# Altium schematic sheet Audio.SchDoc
size A4; Revision: C.2
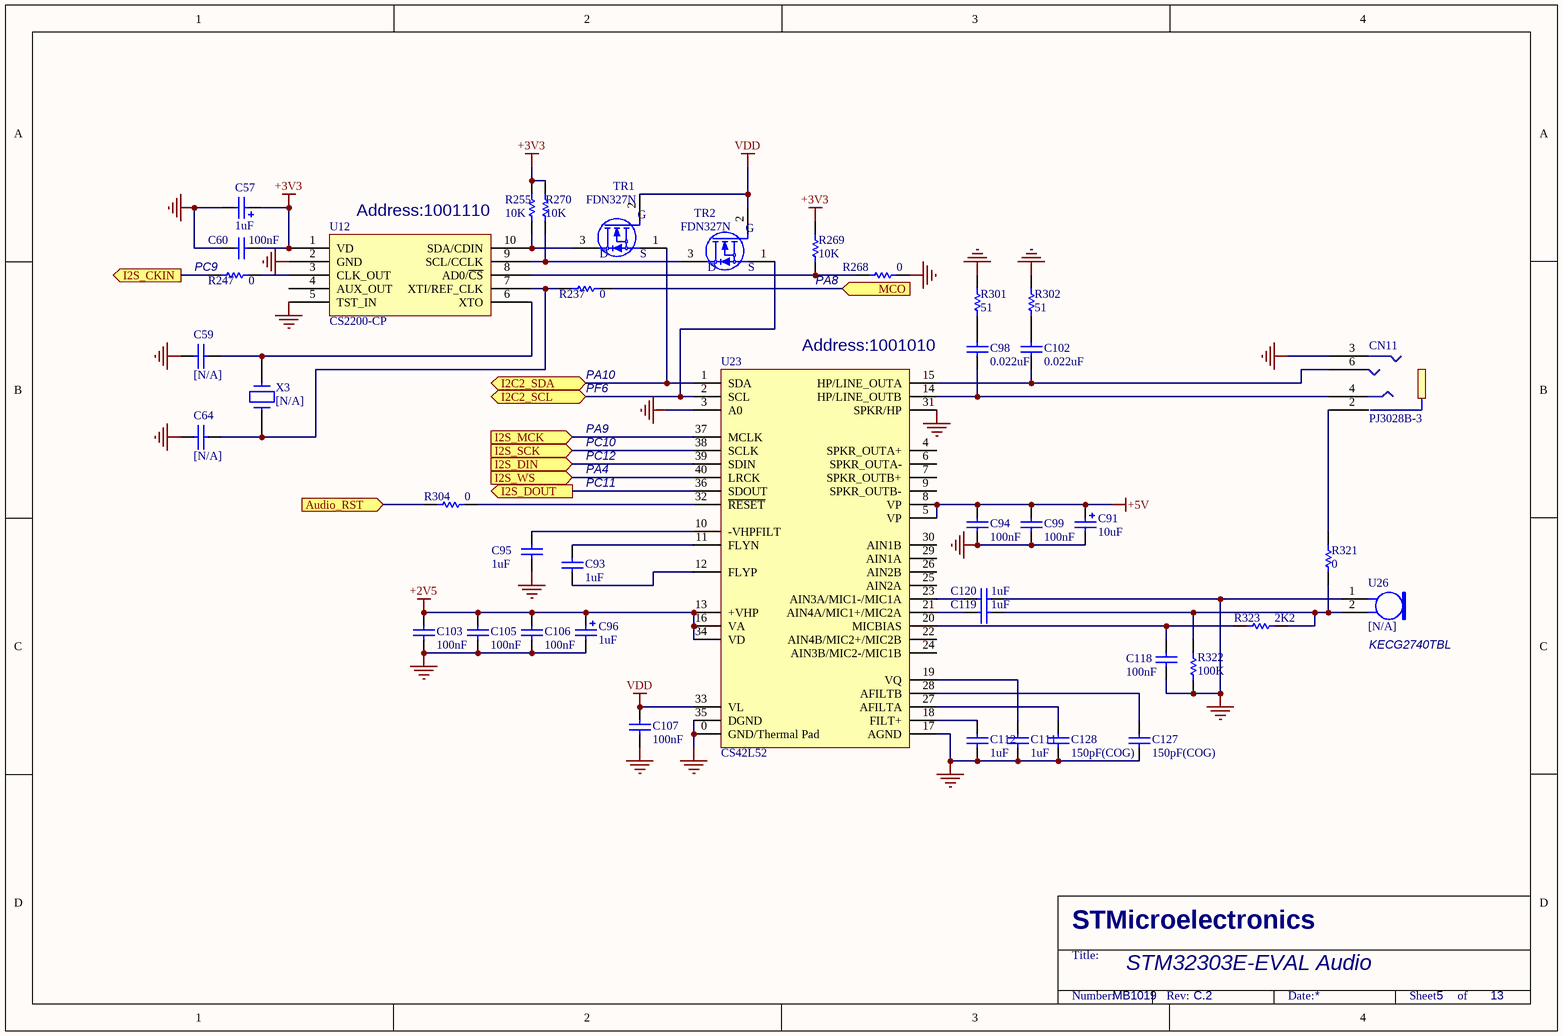
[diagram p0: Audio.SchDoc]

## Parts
C57  1uF  [TAN-A]
C59  [N/A]  [0603C]
C60  100nF  [0603C]
C64  [N/A]  [0603C]
C91  10uF  [TAN-A]
C93  1uF  [0603C]
C94  100nF  [0603C]
C95  1uF  [0603C]
C96  1uF  [TAN-A]
C98  0.022uF  [0603C]
C99  100nF  [0603C]
C102  0.022uF  [0603C]
C103  100nF  [0603C]
C105  100nF  [0603C]
C106  100nF  [0603C]
C107  100nF  [0603C]
C111  1uF  [0603C]
C112  1uF  [0603C]
C118  100nF  [0603C]
C119  1uF  [0603C]
C120  1uF  [0603C]
C127  150pF(COG)  [0603C]
C128  150pF(COG)  [0603C]
CN11  PJ3028B-3  [PJ3028B]
R237  0  [0603R]
R247  0  [0603R]
R255  10K  [0603R]
R268  0  [0603R]
R269  10K  [0603R]
R270  10K  [0603R]
R301  51  [0603R]
R302  51  [0603R]
R304  0  [0603R]
R321  0  [0603R]
R322  100K  [0603R]
R323  2K2  [0603R]
TR1  FDN327N  [SOT-23]
TR2  FDN327N  [SOT-23]
U12  CS2200-CP  [MSOP10(0.5)]
U23  CS42L52  [QFN40(6*6)]
U26  [N/A]  [KEC2740]
X3  [N/A]  [XTAL_socket]

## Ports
Audio_RST (in), I2C2_SCL (bidir), I2C2_SDA (bidir), I2S_CKIN (out), I2S_DIN (in), I2S_DOUT (out), I2S_MCK (in), I2S_SCK (in), I2S_WS (in), MCO (in)

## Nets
+2V5: C96.1 C103.1 C105.1 C106.1 U23.13(+VHP) U23.16(VA) U23.34(VD)
+3V3: C57.1 C60.1 R255.1 R269.1 R270.1 U12.1(VD)
+5V: C91.1 C94.1 C99.1 U23.5(VP) U23.8(VP)
GND: C57.2 C59.2 C60.2 C64.2 C91.2 C94.2 C95.2 C96.2 C99.2 C103.2 C105.2 C106.2 C107.2 C111.1 C112.1 C118.2 C120.2 C127.1 C128.1 CN11.3 R268.1 R301.1 R302.1 R322.2 U12.2(GND) U12.5(TST_IN) U23.0(GND/Thermal_Pad) U23.3(A0) U23.17(AGND) U23.31(SPKR/HP) U23.35(DGND) U26.1
VDD: C107.1 TR1.2(G) TR2.2(G) U23.33(VL)
Audio_RST: R304.2 ; port Audio_RST
I2C2_SCL: TR2.1(S) U23.2(SCL) ; port I2C2_SCL
I2C2_SDA: TR1.1(S) U23.1(SDA) ; port I2C2_SDA
I2S_CKIN: R247.2 ; port I2S_CKIN
I2S_DIN: U23.39(SDIN) ; port I2S_DIN
I2S_DOUT: U23.36(SDOUT) ; port I2S_DOUT
I2S_MCK: U23.37(MCLK) ; port I2S_MCK
I2S_SCK: U23.38(SCLK) ; port I2S_SCK
I2S_WS: U23.40(LRCK) ; port I2S_WS
MCO: R237.1 ; port MCO
NetC59_1: C59.1 U12.6(XTO) X3.2
NetC64_1: C64.1 R237.2 U12.7(XTI/REF_CLK) X3.1
NetC93_1: C93.1 U23.12(FLYP)
NetC93_2: C93.2 U23.11(FLYN)
NetC95_1: C95.1 U23.10(-VHPFILT)
NetC98_1: C98.1 R301.2
NetC98_2: C98.2 CN11.4 U23.14(HP/LINE_OUTB)
NetC102_1: C102.1 R302.2
NetC102_2: C102.2 CN11.6 U23.15(HP/LINE_OUTA)
NetC111_2: C111.2 U23.19(VQ)
NetC112_2: C112.2 U23.18(FILT+)
NetC118_1: C118.1 R323.2 U23.20(MICBIAS)
NetC119_1: C119.1 U23.21(AIN4A/MIC1+/MIC2A)
NetC119_2: C119.2 R321.1 R322.1 R323.1 U26.2
NetC120_1: C120.1 U23.23(AIN3A/MIC1-/MIC1A)
NetC127_2: C127.2 U23.28(AFILTB)
NetC128_2: C128.2 U23.27(AFILTA)
NetCN11_2: CN11.2 R321.2
NetR247_1: R247.1 U12.3(CLK_OUT)
NetR255_2: R255.2 TR1.3(D) U12.10(SDA/CDIN)
NetR268_2: R268.2 R269.2 U12.8(AD0/~{CS})
NetR270_2: R270.2 TR2.3(D) U12.9(SCL/CCLK)
NetR304_1: R304.1 U23.32(~{RESET})

Not connected (* = marked no-connect by the designer): U12 4(AUX_OUT); U23 4(SPKR_OUTA+) 6(SPKR_OUTA-) 7(SPKR_OUTB+) 9(SPKR_OUTB-) 22(AIN4B/MIC2+/MIC2B) 24(AIN3B/MIC2-/MIC1B) 25(AIN2A) 26(AIN2B) 29(AIN1A) 30(AIN1B)

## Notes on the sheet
- (near U12) Address:1001110
- (near R247) PC9
- (near R269) PA8
- PA10
- (near U23) Address:1001010
- PA9
- PC10
- PF6
- PA4
- PC12
- PC11
- (near U26) KECG2740TBL
- STM32303E-EVAL Audio
- MB1019
- 5
- 13

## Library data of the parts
C57 C96 = Cap Pol1: Polarized Capacitor (Radial); Value: 47uF
C59 C60 C64 = CAP: Capacitor
C91 = Cap Pol1: Polarized Capacitor (Radial)
C93 C95 C98 C102 C111 C112 C119 C120 C127 C128 = CAP: Capacitor; Value: 100nF
C94 C99 C103 C105-C107 C118 = Cap: Capacitor; Value: 10nF
R237 R268 R301 R302 R321 R322 = res1: Resistor; Value: 1K
R247 R255 R269 R270 R304 R323 = Res1: Resistor; Value: 1K
TR1 TR2 = 2N7000
U26 = Mic2: Microphone
X3 = CRYSTAL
